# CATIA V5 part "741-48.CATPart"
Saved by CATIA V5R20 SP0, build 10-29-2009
Part number: 741-48
Bounding box of the stored display mesh (mm): x -40 to 40, y -40 to 40, z -47 to 50
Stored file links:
  C:\Users\Utente\Desktop\IO LAVORO\3D X SITO CF\X SITO\741\741-48.CATPart
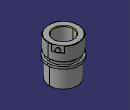
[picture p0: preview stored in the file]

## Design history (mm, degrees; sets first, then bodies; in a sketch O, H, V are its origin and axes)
Set1
  DatumSurface1 to DatumSurface42 "741-48"
Body1 (main body)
